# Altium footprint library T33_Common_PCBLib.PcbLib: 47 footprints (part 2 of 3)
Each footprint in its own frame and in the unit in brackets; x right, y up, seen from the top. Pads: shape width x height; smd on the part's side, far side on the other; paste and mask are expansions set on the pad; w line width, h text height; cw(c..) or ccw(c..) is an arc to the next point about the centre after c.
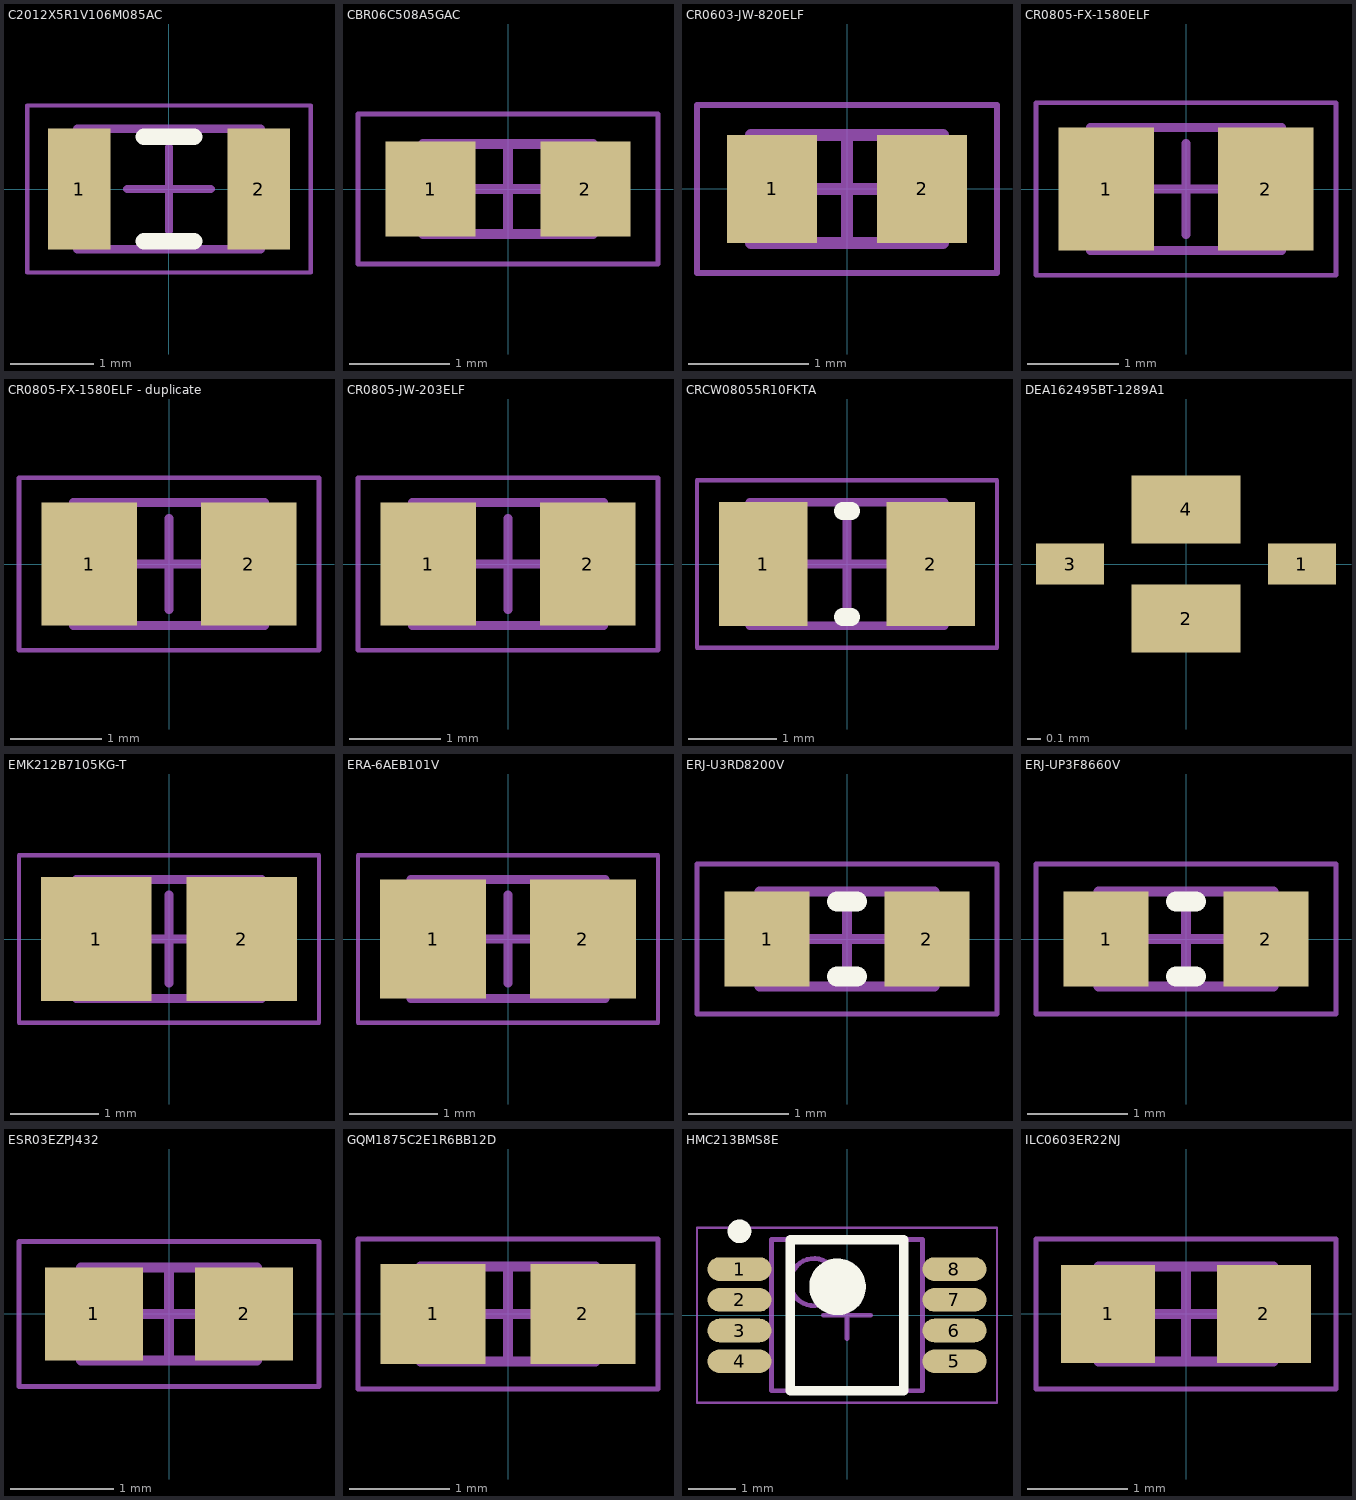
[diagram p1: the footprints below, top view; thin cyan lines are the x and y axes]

## C2012X5R1V106M085AC [mm] "MLCC - SMD/SMT"
height 1.45
pads (2):
  rect 0.75x1.45 smd: 1(-1.075,0) 2(1.075,0)
Top Overlay:
  lines w0.2: -0.3,-0.625 0.3,-0.625 ; -0.3,0.625 0.3,0.625
Mechanical 13:
  lines w0.1: -1.1,-0.725 1.1,-0.725 1.1,0.725 -1.1,0.725 -1.1,-0.725
Mechanical 15:
  lines w0.05: -1.7,-1 1.7,-1 1.7,1 -1.7,1 -1.7,-1
  lines w0.1: -0.5,0 0.5,0 ; 0,-0.5 0,0.5
3D body: height 1.45, standoff 0, extent 0.9,-0.725 1.1,0.725
3D body: height 1.45, standoff 0, extent -1.1,-0.725 -0.9,0.725
3D body: height 1.45, standoff 0, extent -0.9,-0.725 0.9,0.725

## CBR06C508A5GAC [mm] "Multilayer Ceramic Capacitors MLCC - SMD/SMT 50V 0.5pF C0G 0603 0.05pF"
height 0.87
pads (2):
  rect 0.9x0.95 smd: 1(-0.775,0) 2(0.775,0)
Mechanical 13:
  lines w0.1: -0.85,-0.45 -0.85,0.45 0.85,0.45 0.85,-0.45 -0.85,-0.45
Mechanical 15:
  lines w0.05: -1.5,-0.75 -1.5,0.75 1.5,0.75 1.5,-0.75 -1.5,-0.75
  lines w0.1: -0.45,0 0.45,0 ; 0,-0.45 0,0.45
3D body: height 0.87, standoff 0, extent -0.52,-0.45 0.52,0.45
3D body: height 0.87, standoff 0, extent -0.85,-0.45 -0.52,0.45
3D body: height 0.87, standoff 0, extent 0.52,-0.45 0.85,0.45

## CR0603-JW-820ELF [mm] "Thick Film Resistors - SMD 82 OHM 5%"
height 0.8
pads (2):
  rect 0.75x0.9 smd: 1(-0.625,0) 2(0.625,0)
Mechanical 13:
  lines w0.1: -0.8,-0.45 0.8,-0.45 0.8,0.45 -0.8,0.45 -0.8,-0.45
Mechanical 15:
  lines w0.05: -1.25,-0.7 1.25,-0.7 1.25,0.7 -1.25,0.7 -1.25,-0.7
  lines w0.1: -0.45,0 0.45,0 ; 0,-0.45 0,0.45
3D body: height 0.8, standoff 0, extent 0.5,-0.45 0.8,0.45
3D body: height 0.8, standoff 0, extent -0.8,-0.45 -0.5,0.45
3D body: height 0.8, standoff 0, extent -0.5,-0.45 0.5,0.45

## CR0805-FX-1580ELF [mm] "Thick Film Resistors - SMD 158ohm 1%"
height 0.6
pads (2):
  rect 1.05x1.35 smd: 1(-0.875,0) 2(0.875,0)
Mechanical 13:
  lines w0.1: -1.05,-0.675 1.05,-0.675 1.05,0.675 -1.05,0.675 -1.05,-0.675
Mechanical 15:
  lines w0.05: -1.65,-0.95 1.65,-0.95 1.65,0.95 -1.65,0.95 -1.65,-0.95
  lines w0.1: -0.5,0 0.5,0 ; 0,-0.5 0,0.5
3D body: height 0.6, standoff 0, extent 0.65,-0.675 1.05,0.675
3D body: height 0.6, standoff 0, extent -1.05,-0.675 -0.65,0.675
3D body: height 0.6, standoff 0, extent -0.65,-0.675 0.65,0.675

## CR0805-FX-1580ELF - duplicate [mm] "Chip Resistor, 2-Leads, Body 2.00x1.25mm, IPC Medium Density"
height 0.6
pads (2):
  rect 1.05x1.35 smd: 1(-0.875,0) 2(0.875,0)
Mechanical 13:
  lines w0.1: -1.05,-0.675 1.05,-0.675 1.05,0.675 -1.05,0.675 -1.05,-0.675
Mechanical 15:
  lines w0.05: -1.65,-0.95 1.65,-0.95 1.65,0.95 -1.65,0.95 -1.65,-0.95
  lines w0.1: -0.5,0 0.5,0 ; 0,-0.5 0,0.5
3D body: height 0.6, standoff 0, extent 0.65,-0.675 1.05,0.675
3D body: height 0.6, standoff 0, extent -1.05,-0.675 -0.65,0.675
3D body: height 0.6, standoff 0, extent -0.65,-0.675 0.65,0.675

## CR0805-JW-203ELF [mm] "Thick Film Resistors - SMD 20K 5%"
height 0.6
pads (2):
  rect 1.05x1.35 smd: 1(-0.875,0) 2(0.875,0)
Mechanical 13:
  lines w0.1: -1.05,-0.675 1.05,-0.675 1.05,0.675 -1.05,0.675 -1.05,-0.675
Mechanical 15:
  lines w0.05: -1.65,-0.95 1.65,-0.95 1.65,0.95 -1.65,0.95 -1.65,-0.95
  lines w0.1: -0.5,0 0.5,0 ; 0,-0.5 0,0.5
3D body: height 0.6, standoff 0, extent 0.65,-0.675 1.05,0.675
3D body: height 0.6, standoff 0, extent -1.05,-0.675 -0.65,0.675
3D body: height 0.6, standoff 0, extent -0.65,-0.675 0.65,0.675

## CRCW08055R10FKTA [mm] "Thick Film Resistors - SMD 1/8watt 5.1ohms 1%"
height 0.5
pads (2):
  rect 1x1.4 smd: 1(-0.95,0) 2(0.95,0)
Top Overlay:
  lines w0.2: -0.05,-0.6 0.05,-0.6 ; -0.05,0.6 0.05,0.6
Mechanical 13:
  lines w0.1: -1.1,-0.7 1.1,-0.7 1.1,0.7 -1.1,0.7 -1.1,-0.7
Mechanical 15:
  lines w0.05: -1.7,-0.95 1.7,-0.95 1.7,0.95 -1.7,0.95 -1.7,-0.95
  lines w0.1: -0.5,0 0.5,0 ; 0,-0.5 0,0.5
3D body: height 0.5, standoff 0, extent 0.75,-0.7 1.1,0.7
3D body: height 0.5, standoff 0, extent -1.1,-0.7 -0.75,0.7
3D body: height 0.5, standoff 0, extent -0.75,-0.7 0.75,0.7

## DEA162495BT-1289A1 [mm] "Multilayer Band Pass Filter  For 2300-2690MHz"
height 1
pads (4):
  rect 0.5x0.3 smd: 1(0.85,0) 3(-0.85,0)
  rect 0.8x0.5 smd: 2(0,-0.4) 4(0,0.4)

## EMK212B7105KG-T [mm] "MLCC - SMD/SMT 0805 16VDC 1uF 10% X7R"
height 0.94
pads (2):
  rect 1.25x1.4 smd: 1(-0.825,0) 2(0.825,0)
Mechanical 13:
  lines w0.1: -1.05,-0.675 -1.05,0.675 1.05,0.675 1.05,-0.675 -1.05,-0.675
Mechanical 15:
  lines w0.05: -1.7,-0.95 -1.7,0.95 1.7,0.95 1.7,-0.95 -1.7,-0.95
  lines w0.1: -0.5,0 0.5,0 ; 0,-0.5 0,0.5
3D body: height 0.94, standoff 0, extent -0.55,-0.675 0.55,0.675
3D body: height 0.94, standoff 0, extent -1.05,-0.675 -0.55,0.675
3D body: height 0.94, standoff 0, extent 0.55,-0.675 1.05,0.675

## ERA-6AEB101V [mm] "Thin Film Resistors - SMD 0805 1/8W 100ohms"
height 0.6
pads (2):
  rect 1.2x1.35 smd: 1(-0.85,0) 2(0.85,0)
Mechanical 13:
  lines w0.1: -1.1,-0.675 -1.1,0.675 1.1,0.675 1.1,-0.675 -1.1,-0.675
Mechanical 15:
  lines w0.05: -1.7,-0.95 -1.7,0.95 1.7,0.95 1.7,-0.95 -1.7,-0.95
  lines w0.1: -0.5,0 0.5,0 ; 0,-0.5 0,0.5
3D body: height 0.6, standoff 0, extent -0.7,-0.675 0.7,0.675
3D body: height 0.6, standoff 0, extent -1.1,-0.675 -0.7,0.675
3D body: height 0.6, standoff 0, extent 0.7,-0.675 1.1,0.675

## ERJ-U3RD8200V [mm] "Thick Film Resistors - SMD 0603 Anti-sulfur"
height 0.55
pads (2):
  rect 0.85x0.95 smd: 1(-0.8,0) 2(0.8,0)
Top Overlay:
  lines w0.2: -0.1,-0.375 0.1,-0.375 ; -0.1,0.375 0.1,0.375
Mechanical 13:
  lines w0.1: -0.875,-0.475 -0.875,0.475 0.875,0.475 0.875,-0.475 -0.875,-0.475
Mechanical 15:
  lines w0.05: -1.5,-0.75 -1.5,0.75 1.5,0.75 1.5,-0.75 -1.5,-0.75
  lines w0.1: -0.475,0 0.475,0 ; 0,-0.475 0,0.475
3D body: height 0.55, standoff 0, extent -0.625,-0.475 0.625,0.475
3D body: height 0.55, standoff 0, extent -0.875,-0.475 -0.625,0.475
3D body: height 0.55, standoff 0, extent 0.625,-0.475 0.875,0.475

## ERJ-UP3F8660V [mm] "Thick Film Resistors - SMD 0603 0.25W 1% 866ohm AEC-Q200"
height 0.55
pads (2):
  rect 0.85x0.95 smd: 1(-0.8,0) 2(0.8,0)
Top Overlay:
  lines w0.2: -0.1,-0.375 0.1,-0.375 ; -0.1,0.375 0.1,0.375
Mechanical 13:
  lines w0.1: -0.875,-0.475 -0.875,0.475 0.875,0.475 0.875,-0.475 -0.875,-0.475
Mechanical 15:
  lines w0.05: -1.5,-0.75 -1.5,0.75 1.5,0.75 1.5,-0.75 -1.5,-0.75
  lines w0.1: -0.475,0 0.475,0 ; 0,-0.475 0,0.475
3D body: height 0.55, standoff 0, extent -0.625,-0.475 0.625,0.475
3D body: height 0.55, standoff 0, extent -0.875,-0.475 -0.625,0.475
3D body: height 0.55, standoff 0, extent 0.625,-0.475 0.875,0.475

## ESR03EZPJ432 [mm] "Thick FilmResistors - SMD 0603 4.3Kohm 5% Anti Surge AEC-Q200"
height 0.55
pads (2):
  rect 0.95x0.9 smd: 1(-0.725,0) 2(0.725,0)
Mechanical 13:
  lines w0.1: -0.85,-0.45 -0.85,0.45 0.85,0.45 0.85,-0.45 -0.85,-0.45
Mechanical 15:
  lines w0.05: -1.45,-0.7 -1.45,0.7 1.45,0.7 1.45,-0.7 -1.45,-0.7
  lines w0.1: -0.45,0 0.45,0 ; 0,-0.45 0,0.45
3D body: height 0.55, standoff 0, extent -0.55,-0.45 0.55,0.45
3D body: height 0.55, standoff 0, extent -0.85,-0.45 -0.55,0.45
3D body: height 0.55, standoff 0, extent 0.55,-0.45 0.85,0.45

## GQM1875C2E1R6BB12D [mm] "Multilayer Ceramic Capacitors MLCC - SMD/SMT 0603 1.6pF 250volts C0G 0.1pF"
height 0.8
pads (2):
  rect 1.05x1 smd: 1(-0.75,0) 2(0.75,0)
Mechanical 13:
  lines w0.1: -0.875,-0.475 -0.875,0.475 0.875,0.475 0.875,-0.475 -0.875,-0.475
Mechanical 15:
  lines w0.05: -1.5,-0.75 -1.5,0.75 1.5,0.75 1.5,-0.75 -1.5,-0.75
  lines w0.1: -0.475,0 0.475,0 ; 0,-0.475 0,0.475
3D body: height 0.8, standoff 0, extent -0.525,-0.475 0.525,0.475
3D body: height 0.8, standoff 0, extent -0.875,-0.475 -0.525,0.475
3D body: height 0.8, standoff 0, extent 0.525,-0.475 0.875,0.475

## HMC213BMS8E [mm] "1.5 GHz to 4.5 GHz, GaAs, MMIC,  Double Balanced Mixer"
height 1.1
pads (8):
  oval 1.35x0.5 smd: 1(-2.275,0.975) 2(-2.275,0.325) 3(-2.275,-0.325) 4(-2.275,-0.975) 5(2.275,-0.975) 6(2.275,-0.325) 7(2.275,0.325) 8(2.275,0.975)
Top Overlay:
  circle w0.6: c-0.2,0.6 r0.3
  circle w0.25: c-2.275,1.775 r0.125
  lines w0.2: -1.2,-1.6 1.2,-1.6 1.2,1.6 -1.2,1.6 -1.2,-1.6
Mechanical 13:
  circle w0.1: c-0.7,0.7 r0.5
  lines w0.1: -1.6,-1.6 1.6,-1.6 1.6,1.6 -1.6,1.6 -1.6,-1.6
Mechanical 15:
  lines w0.05: -3.175,-1.85 3.175,-1.85 3.175,1.85 -3.175,1.85 -3.175,-1.85
  lines w0.1: -0.5,0 0.5,0 ; 0,-0.5 0,0.5
3D body: height 1.1, standoff 0.15, extent -1.6,-1.6 1.6,1.6

## ILC0603ER22NJ [mm] "Fixed Inductors 22nH 5%"
height 0.8
pads (2):
  rect 0.94x0.98 smd: 1(-0.78,0) 2(0.78,0)
Mechanical 13:
  lines w0.1: -0.875,-0.475 -0.875,0.475 0.875,0.475 0.875,-0.475 -0.875,-0.475
Mechanical 15:
  lines w0.05: -1.5,-0.75 -1.5,0.75 1.5,0.75 1.5,-0.75 -1.5,-0.75
  lines w0.1: -0.475,0 0.475,0 ; 0,-0.475 0,0.475
3D body: height 0.8, standoff 0, extent -0.525,-0.475 0.525,0.475
3D body: height 0.8, standoff 0, extent -0.875,-0.475 -0.525,0.475
3D body: height 0.8, standoff 0, extent 0.525,-0.475 0.875,0.475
